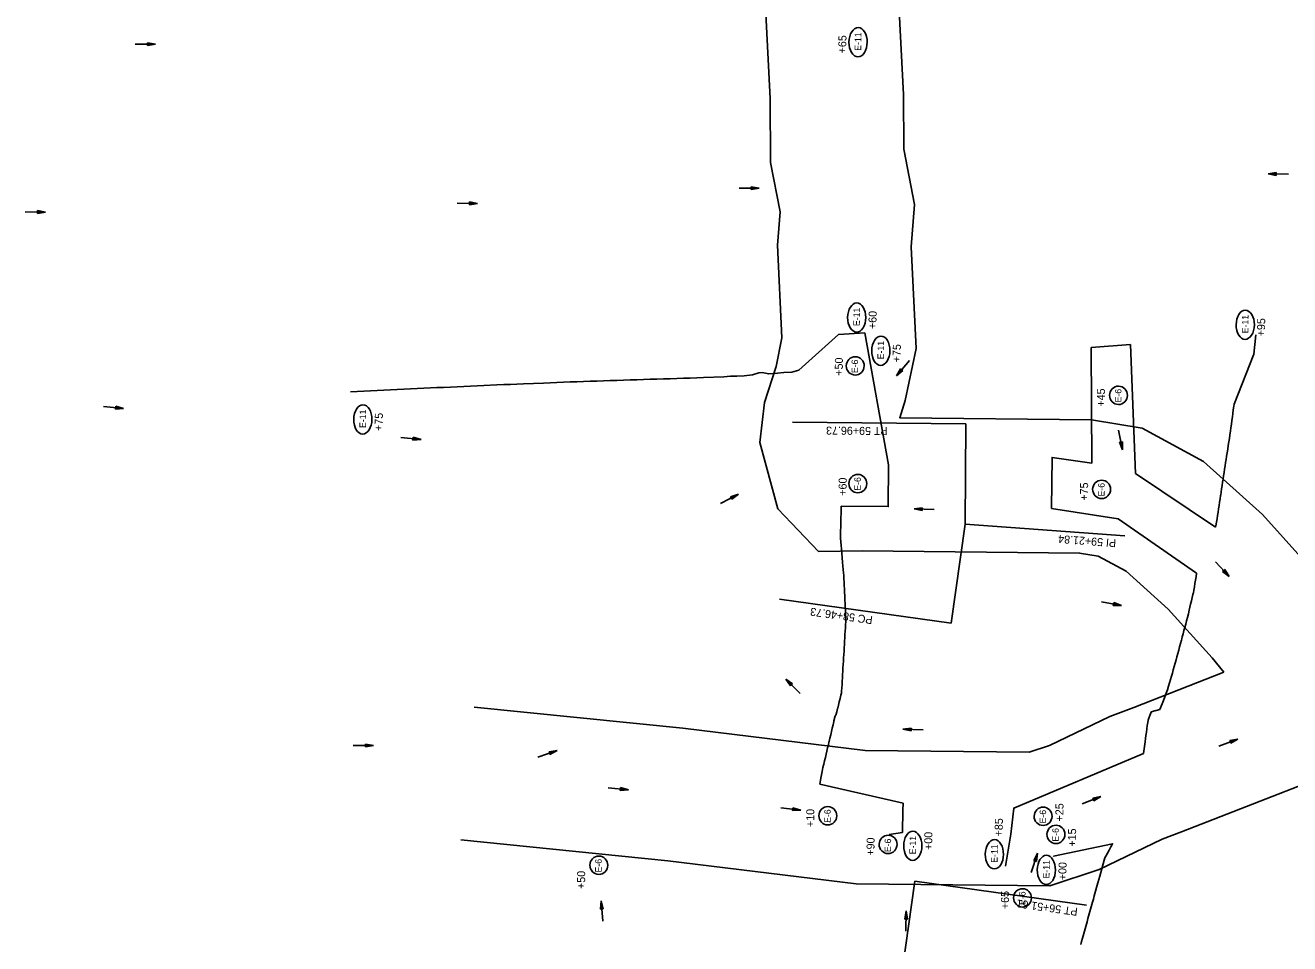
# Model space of a CAD drawing. Extents: x 1312891 to 1314734, y 2088044 to 2090982.
# Drawn here: x 1313292 to 1314240, y 2088726 to 2089414 of the extents above; entities that cross this region are included whole.
import ezdxf

# ---------------------------------------------------------------- set-up
doc = ezdxf.new("R2010")
doc.units = 0
for name, color, linetype in [('43', 7, 'Continuous'), ('44', 7, 'Continuous'), ('Level 1', 7, 'Continuous'), ('Level 44', 7, 'Continuous'), ('R_Buffer', 7, 'Continuous'), ('R_Horz Alg Annot_Detour', 7, 'Continuous')]:
    doc.layers.add(name, color=color, linetype=linetype)

msp = doc.modelspace()

# ---------------------------------------------------------------- linework, layer by layer
at = {"layer": '43'}
for p, q in [((1313383.35, 2089398.89), (1313383.37, 2089401.03)), ((1313389.43, 2089399.91), (1313383.35, 2089398.89)), ((1313383.37, 2089401.03), (1313389.43, 2089399.91)), ((1314223.52, 2089302.72), (1314229.6, 2089303.74)), ((1314229.59, 2089301.59), (1314223.52, 2089302.72)), ((1314229.6, 2089303.74), (1314229.59, 2089301.59)), ((1313835.91, 2089290.97), (1313835.93, 2089293.12)), ((1313842, 2089291.99), (1313835.91, 2089290.97)), ((1313835.93, 2089293.12), (1313842, 2089291.99)), ((1313624.72, 2089279.59), (1313624.74, 2089281.73)), ((1313630.8, 2089280.61), (1313624.72, 2089279.59)), ((1313624.74, 2089281.73), (1313630.8, 2089280.61)), ((1313300.87, 2089273.06), (1313300.89, 2089275.21)), ((1313306.96, 2089274.08), (1313300.87, 2089273.06)), ((1313300.89, 2089275.21), (1313306.96, 2089274.08)), ((1313944.75, 2089151.39), (1313947.91, 2089156.69)), ((1313949.53, 2089155.29), (1313944.75, 2089151.39)), ((1313947.91, 2089156.69), (1313949.53, 2089155.29)), ((1313359.29, 2089126.35), (1313359.53, 2089128.48)), ((1313365.45, 2089126.73), (1313359.29, 2089126.35)), ((1313359.53, 2089128.48), (1313365.45, 2089126.73)), ((1313582.31, 2089103.12), (1313582.55, 2089105.25)), ((1313588.47, 2089103.5), (1313582.31, 2089103.12)), ((1313582.55, 2089105.25), (1313588.47, 2089103.5)), ((1314112.13, 2089101.49), (1314114.24, 2089101.92)), ((1314114.4, 2089095.75), (1314112.13, 2089101.49)), ((1314114.24, 2089101.92), (1314114.4, 2089095.75)), ((1313820.44, 2089060.76), (1313826.32, 2089062.63)), ((1313821.43, 2089058.86), (1313820.44, 2089060.76)), ((1313826.32, 2089062.63), (1313821.43, 2089058.86)), ((1313958.03, 2089051.56), (1313964.14, 2089052.45)), ((1313964.07, 2089050.31), (1313958.03, 2089051.56)), ((1313964.14, 2089052.45), (1313964.07, 2089050.31)), ((1314189.34, 2089004.61), (1314190.9, 2089006.08)), ((1314194.27, 2089000.91), (1314189.34, 2089004.61)), ((1314190.9, 2089006.08), (1314194.27, 2089000.91)), ((1314107.3, 2088979.24), (1314107.69, 2088981.35)), ((1314113.46, 2088979.17), (1314107.3, 2088979.24)), ((1314107.69, 2088981.35), (1314113.46, 2088979.17)), ((1313861.82, 2088924), (1313866.88, 2088920.46)), ((1313865.36, 2088918.94), (1313861.82, 2088924)), ((1313866.88, 2088920.46), (1313865.36, 2088918.94)), ((1313949.72, 2088886.45), (1313955.83, 2088887.35)), ((1313955.76, 2088885.2), (1313949.72, 2088886.45)), ((1313955.83, 2088887.35), (1313955.76, 2088885.2)), ((1314194.65, 2088877.97), (1314200.72, 2088879.11)), ((1314200.72, 2088879.11), (1314195.41, 2088875.97)), ((1313546.72, 2088873.13), (1313546.74, 2088875.28)), ((1313552.8, 2088874.15), (1313546.72, 2088873.13)), ((1313546.74, 2088875.28), (1313552.8, 2088874.15)), ((1313684.38, 2088869.48), (1313690.47, 2088870.46)), ((1313685.08, 2088867.46), (1313684.38, 2088869.48)), ((1313690.47, 2088870.46), (1313685.08, 2088867.46)), ((1314195.41, 2088875.97), (1314194.65, 2088877.97)), ((1313737.7, 2088840.52), (1313737.95, 2088842.65)), ((1313743.86, 2088840.9), (1313737.7, 2088840.52)), ((1313737.95, 2088842.65), (1313743.86, 2088840.9)), ((1314092.09, 2088834.81), (1314098.16, 2088835.95)), ((1314092.85, 2088832.81), (1314092.09, 2088834.81)), ((1314098.16, 2088835.95), (1314092.85, 2088832.81)), ((1313867, 2088825.5), (1313867.24, 2088827.64)), ((1313873.16, 2088825.88), (1313867, 2088825.5)), ((1313867.24, 2088827.64), (1313873.16, 2088825.88)), ((1314047.71, 2088788.09), (1314050.68, 2088793.5)), ((1314050.68, 2088793.5), (1314049.74, 2088787.4)), ((1314049.74, 2088787.4), (1314047.71, 2088788.09)), ((1313722.88, 2088751.59), (1313723.47, 2088757.73)), ((1313723.47, 2088757.73), (1313725.02, 2088751.76)), ((1313725.02, 2088751.76), (1313722.88, 2088751.59)), ((1313951.01, 2088744.17), (1313952.17, 2088750.23)), ((1313952.17, 2088750.23), (1313953.15, 2088744.14)), ((1313953.15, 2088744.14), (1313951.01, 2088744.17))]:
    msp.add_line(p, q, dxfattribs=at)
for points in [[(1313374.25, 2089400.04), (1313389.43, 2089399.91)], [(1314238.71, 2089302.58), (1314223.52, 2089302.72)], [(1313826.81, 2089292.12), (1313842, 2089291.99)], [(1313615.62, 2089280.74), (1313630.8, 2089280.61)], [(1313291.77, 2089274.22), (1313306.96, 2089274.08)], [(1313954.67, 2089162.88), (1313944.75, 2089151.39)], [(1313350.36, 2089128.44), (1313365.45, 2089126.73)], [(1314111.36, 2089110.63), (1314114.4, 2089095.75)], [(1313573.38, 2089105.21), (1313588.47, 2089103.5)], [(1313812.86, 2089055.59), (1313826.32, 2089062.63)], [(1313973.21, 2089051.11), (1313958.03, 2089051.56)], [(1314183.9, 2089012), (1314194.27, 2089000.91)], [(1314098.54, 2088981.99), (1314113.46, 2088979.17)], [(1313872.56, 2088913.25), (1313861.82, 2088924)], [(1313964.9, 2088886.01), (1313949.72, 2088886.45)], [(1314186.5, 2088873.76), (1314200.72, 2088879.11)], [(1313537.62, 2088874.28), (1313552.8, 2088874.15)], [(1313676.12, 2088865.49), (1313690.47, 2088870.46)], [(1313728.77, 2088842.61), (1313743.86, 2088840.9)], [(1314083.94, 2088830.6), (1314098.16, 2088835.95)], [(1313858.07, 2088827.6), (1313873.16, 2088825.88)], [(1314045.8, 2088779.11), (1314050.68, 2088793.5)], [(1313724.68, 2088742.59), (1313723.47, 2088757.73)], [(1313951.95, 2088735.04), (1313952.17, 2088750.23)]]:
    msp.add_lwpolyline(points, dxfattribs=at)
at = {"layer": 'Level 1'}
for centre, major_axis, ratio in [((1313916.05, 2089401.39), (0.1, 10.96), 0.622952), ((1313915.02, 2089195.05), (0.1, 10.96), 0.622952), ((1314206.3, 2089189.59), (0.1, 10.96), 0.622952), ((1313933.12, 2089170.15), (0.1, 10.96), 0.622952), ((1313913.93, 2089158.78), (-0.05, -6.88), 0.97521), ((1314111.27, 2089136.72), (-0.05, -6.88), 0.97521), ((1313544.81, 2089118.67), (0.1, 10.96), 0.622952), ((1313915.87, 2089070.56), (-0.05, -6.88), 0.97521), ((1314098.63, 2089066.22), (-0.05, -6.88), 0.97521), ((1313893.37, 2088821.58), (-0.05, -6.88), 0.97521), ((1314054.76, 2088821.18), (-0.05, -6.88), 0.97521), ((1314064.39, 2088807.64), (-0.05, -6.88), 0.97521), ((1313938.58, 2088800.14), (-0.05, -6.88), 0.97521), ((1313957.08, 2088799.07), (0.1, 10.96), 0.622952), ((1314018.24, 2088792.71), (0.1, 10.96), 0.622952), ((1313721.73, 2088784.51), (-0.05, -6.88), 0.97521), ((1314057.2, 2088780.97), (0.1, 10.96), 0.622952), ((1314039.34, 2088760.06), (-0.05, -6.88), 0.97521)]:
    msp.add_ellipse(centre, major_axis=major_axis, ratio=ratio, dxfattribs=at)
at = {"layer": 'Level 44'}
for points in [[(1313921.2, 2089183.57), (1313901.47, 2089182.32), (1313871.6, 2089155.47)], [(1313921.2, 2089183.57), (1313938.94, 2089084.52), (1313938.67, 2089053.36), (1313903.27, 2089053.67)], [(1314184.04, 2089037.96), (1314184.24, 2089038.99), (1314184.73, 2089041.63), (1314185.14, 2089044.24), (1314185.53, 2089046.72), (1314185.92, 2089049.2), (1314186.3, 2089051.68), (1314186.68, 2089054.16), (1314187.07, 2089056.64), (1314187.45, 2089059.12), (1314187.82, 2089061.6), (1314187.91, 2089062.19), (1314188.2, 2089064.08), (1314188.57, 2089066.56), (1314188.95, 2089069.04), (1314189.32, 2089071.52), (1314189.69, 2089074), (1314190.06, 2089076.49), (1314190.42, 2089078.97), (1314190.78, 2089081.43), (1314191.15, 2089083.88), (1314191.51, 2089086.29), (1314191.9, 2089088.66), (1314192.32, 2089091.09), (1314192.76, 2089093.65), (1314193.18, 2089096.38), (1314193.58, 2089099.06), (1314193.99, 2089101.74), (1314194.38, 2089104.41), (1314194.77, 2089107.09), (1314195.16, 2089109.77), (1314195.54, 2089112.45), (1314195.91, 2089115.14), (1314196.28, 2089117.81), (1314196.65, 2089120.49), (1314197.01, 2089123.18), (1314197.37, 2089125.86), (1314197.72, 2089128.55), (1314197.91, 2089130), (1314212.7, 2089167.68), (1314214.29, 2089182.11), (1314214.29, 2089182.11)], [(1314061.11, 2089051.99), (1314061.44, 2089090.23), (1314091.2, 2089085.95), (1314091.2, 2089085.95), (1314091.2, 2089085.95), (1314090.86, 2089172.5), (1314120.27, 2089174.81), (1314124.07, 2089078.23)], [(1313871.6, 2089155.47), (1313866.33, 2089154.01), (1313860.44, 2089153.77), (1313855.7, 2089153.33), (1313849.16, 2089152.73), (1313844.11, 2089153.86), (1313841.75, 2089153.63), (1313837.03, 2089152.15), (1313830.67, 2089151.26), (1313825.13, 2089151.13), (1313820.38, 2089150.98), (1313815.42, 2089150.62), (1313800.25, 2089150.04), (1313795.24, 2089149.86), (1313790.24, 2089149.68), (1313785.25, 2089149.5), (1313780.23, 2089149.32), (1313775.13, 2089149.16), (1313770.15, 2089149.08), (1313765.24, 2089148.91), (1313760.25, 2089148.73), (1313755.23, 2089148.56), (1313750.19, 2089148.4), (1313745.19, 2089148.27), (1313740.24, 2089148.11), (1313735.26, 2089147.93), (1313730.21, 2089147.75), (1313725.23, 2089147.63), (1313720.26, 2089147.43), (1313715.24, 2089147.27), (1313710.27, 2089147.1), (1313705.28, 2089146.92), (1313700.32, 2089146.73), (1313695.33, 2089146.52), (1313690.31, 2089146.33), (1313685.3, 2089146.14), (1313680.31, 2089145.95), (1313665.32, 2089145.37), (1313660.35, 2089145.18), (1313655.4, 2089144.96), (1313650.39, 2089144.73), (1313645.38, 2089144.53), (1313635.44, 2089144.11), (1313630.47, 2089143.85), (1313625.46, 2089143.61), (1313620.51, 2089143.36), (1313610.41, 2089142.82), (1313605.29, 2089142.67), (1313600.4, 2089142.52), (1313595.52, 2089142.29), (1313590.55, 2089142.02), (1313585.51, 2089141.75), (1313580.46, 2089141.53), (1313575.51, 2089141.31), (1313565.57, 2089140.8), (1313560.49, 2089140.53), (1313555.47, 2089140.35), (1313550.52, 2089140.11), (1313535.59, 2089139.46)], [(1314124.07, 2089078.23), (1314184.04, 2089037.96)], [(1313903.27, 2089053.67), (1313903.35, 2089050.14), (1313903.32, 2089047.91), (1313903.23, 2089045.44), (1313903.18, 2089042.84), (1313903.14, 2089040.36), (1313902.95, 2089032.8), (1313902.92, 2089029.76), (1313903.36, 2089024.24), (1313903.56, 2089021.73), (1313904.32, 2089011.58), (1313904.54, 2089008.7), (1313905.26, 2089003.75)], [(1314129.98, 2088868.26), (1314131.19, 2088876.9), (1314131.54, 2088879.39), (1314131.88, 2088881.87), (1314132.23, 2088884.36), (1314132.57, 2088886.84), (1314132.9, 2088889.27), (1314133.22, 2088891.42), (1314133.6, 2088893.28), (1314134.03, 2088894.85), (1314134.79, 2088896.75), (1314135.75, 2088899.16), (1314135.83, 2088899.37), (1314142.23, 2088901.14), (1314145.07, 2088908.1), (1314146.1, 2088910.64), (1314147.13, 2088913.39), (1314148, 2088916.07), (1314148.81, 2088918.64), (1314149.56, 2088921.21), (1314150.27, 2088923.69), (1314150.96, 2088926.13), (1314151.65, 2088928.58), (1314152.34, 2088931.02), (1314153.03, 2088933.47), (1314153.72, 2088935.92), (1314154.4, 2088938.36), (1314155.08, 2088940.81), (1314155.76, 2088943.26), (1314156.44, 2088945.71), (1314157.12, 2088948.16), (1314157.79, 2088950.63), (1314158.46, 2088953.1), (1314158.76, 2088954.22), (1314159.13, 2088955.67), (1314159.73, 2088958.07), (1314160.35, 2088960.38), (1314161.02, 2088962.75), (1314161.71, 2088965.19), (1314162.39, 2088967.64), (1314163.11, 2088970.19), (1314163.84, 2088973.05), (1314164.36, 2088975.78), (1314164.8, 2088978.02), (1314165.34, 2088980.28), (1314165.92, 2088982.68), (1314166.51, 2088985.1), (1314167.12, 2088987.55), (1314167.26, 2088988.13), (1314167.42, 2088988.78), (1314167.75, 2088990.64), (1314168.2, 2088993.13), (1314168.63, 2088995.63), (1314169.06, 2088998.15), (1314169.49, 2089000.75), (1314169.86, 2089003.35), (1314111.16, 2089044.05), (1314061.11, 2089051.99)], [(1313905.26, 2089003.75), (1313905.35, 2089001.73), (1313905.46, 2088999.2), (1313905.57, 2088996.64), (1313905.7, 2088994.09), (1313905.82, 2088991.57), (1313905.93, 2088989.07), (1313906.05, 2088986.53), (1313906.16, 2088984), (1313906.23, 2088982.55), (1313906.28, 2088981.44), (1313906.41, 2088978.94), (1313906.61, 2088973.94), (1313906.72, 2088971.4), (1313906.81, 2088969.06), (1313906.82, 2088967.05), (1313906.69, 2088964.88), (1313906.54, 2088962.37), (1313906.39, 2088959.86), (1313906.24, 2088957.36), (1313906.1, 2088954.86), (1313905.95, 2088952.35), (1313905.81, 2088949.84), (1313905.67, 2088947.34), (1313905.53, 2088944.85), (1313905.38, 2088942.4), (1313905.22, 2088939.92), (1313905.06, 2088937.38), (1313904.91, 2088934.88), (1313904.76, 2088932.37), (1313904.62, 2088929.87), (1313904.47, 2088927.36), (1313904.33, 2088924.86), (1313904.18, 2088922.35), (1313904.04, 2088919.87), (1313903.89, 2088917.41), (1313903.73, 2088914.88), (1313903.65, 2088913.36), (1313903.26, 2088911.89), (1313902.62, 2088909.42), (1313901.98, 2088906.96), (1313901.34, 2088904.49), (1313900.78, 2088902.26), (1313900.71, 2088902.01), (1313900.09, 2088899.55), (1313899.46, 2088897.02), (1313898.88, 2088896.39), (1313897.98, 2088892.66), (1313897.86, 2088892.16), (1313897.27, 2088889.7), (1313896.68, 2088887.23), (1313896.1, 2088884.76), (1313895.52, 2088882.29), (1313894.95, 2088879.82), (1313894.38, 2088877.35), (1313894.26, 2088876.85), (1313893.81, 2088874.87), (1313893.26, 2088872.4), (1313892.73, 2088870.06), (1313892.16, 2088867.74), (1313891.54, 2088865.3), (1313890.92, 2088862.84), (1313890.31, 2088860.38), (1313889.64, 2088857.64), (1313889.12, 2088854.87), (1313888.66, 2088852.37), (1313888.22, 2088849.89), (1313887.41, 2088845.35), (1313949.75, 2088830.93)], [(1314026.65, 2088783.78), (1314030.52, 2088807.76), (1314032.73, 2088827.37), (1314129.98, 2088868.26)], [(1313949.75, 2088830.93), (1313949.7, 2088825.84), (1313949.32, 2088809.12), (1313939.25, 2088807.64)], [(1314082.98, 2088725.07), (1314083.64, 2088727.39), (1314084.35, 2088729.86), (1314087.74, 2088742.11), (1314088.42, 2088744.55), (1314091.8, 2088756.75), (1314092.48, 2088759.19), (1314093.16, 2088761.64), (1314095.85, 2088771.4), (1314096.51, 2088773.8), (1314097.21, 2088776.24), (1314100.57, 2088788.42), (1314101.01, 2088789.94), (1314101.7, 2088791.33), (1314104.2, 2088795.88), (1314105.49, 2088798.24), (1314106.8, 2088800.6), (1314062.46, 2088791.33), (1314062.46, 2088791.33)]]:
    msp.add_lwpolyline(points, dxfattribs=at)
at = {"layer": 'R_Buffer'}
for points in [[(1314398.07, 2088926.4), (1314279.08, 2088981.02), (1314219.25, 2089047.46), (1314174.9, 2089087.16), (1314129.03, 2089112.05), (1314090.93, 2089118.43), (1313947.29, 2089119.91), (1313951.49, 2089132.93), (1313959.52, 2089171.91), (1313955.89, 2089247.91), (1313958.34, 2089279.86), (1313950.38, 2089321.29), (1313950.04, 2089362.11), (1313946.13, 2089439.68), (1313939.37, 2089474.77), (1313935.33, 2089518.66), (1313906.32, 2089564.88), (1313890.91, 2089585.64), (1313842.78, 2089656.54), (1313803.18, 2089711.63), (1313763.93, 2089776.35), (1313748.13, 2089794.9), (1313663.53, 2089824.18)], [(1314190.14, 2088929.12), (1314181.4, 2088940.05), (1314148.54, 2088976.54), (1314116.93, 2089004.84), (1314096.02, 2089016.18), (1314082.1, 2089018.52), (1313919.02, 2089020.19), (1313886.42, 2089019.59), (1313855.95, 2089051.66), (1313842.49, 2089101.4), (1313845.88, 2089131.29), (1313854.65, 2089158.45), (1313859.03, 2089179.73), (1313855.71, 2089249.36), (1313857.61, 2089274.15), (1313850.46, 2089311.35), (1313850.06, 2089359.17), (1313846.61, 2089427.64)], [(1314190.14, 2088929.12), (1314122.8, 2088902.8), (1314104.78, 2088896.02), (1314059.46, 2088874.32), (1314044.29, 2088869.32), (1313921.3, 2088870.45), (1313784.65, 2088887.22), (1313628.26, 2088902.96)], [(1314295.86, 2088863.28), (1314241.12, 2088841.68), (1314158.61, 2088809.43), (1314144.05, 2088803.95), (1314096.86, 2088781.35), (1314059.89, 2088769.17), (1313914.73, 2088770.51), (1313773.56, 2088787.83), (1313618.24, 2088803.47)]]:
    msp.add_lwpolyline(points, dxfattribs=at)
at = {"layer": 'R_Horz Alg Annot_Detour'}
for points in [[(1313996.9, 2089115.37), (1313866.91, 2089116.51)], [(1313985.8, 2088965.89), (1313996.25, 2089040.27), (1313996.9, 2089115.37)], [(1313996.25, 2089040.27), (1314115.92, 2089031.38)], [(1313985.8, 2088965.89), (1313857.06, 2088983.99)], [(1313956.03, 2088473.54), (1313937.64, 2088623.28), (1313958.64, 2088772.67)], [(1313958.64, 2088772.67), (1314087.38, 2088754.58)]]:
    msp.add_lwpolyline(points, dxfattribs=at)

# ---------------------------------------------------------------- texts
at = {"layer": '44'}
for s, rotation, p in [('+65', 88.324, (1313907.03, 2089392.97)), ('+60', 88.324, (1313929.68, 2089186.31)), ('+95', 88.324, (1314220.96, 2089180.85)), ('+75', 88.324, (1313947.79, 2089161.41)), ('+50', 89.5, (1313904.58, 2089151.4)), ('+45', 89.5, (1314101.04, 2089128.24)), ('+75', 88.324, (1313559.48, 2089109.93)), ('+60', 89.5, (1313907.43, 2089061.43)), ('+75', 89.5, (1314088.4, 2089057.74)), ('+10', 89.5, (1313883.14, 2088813.1)), ('+25', 89.5, (1314069.95, 2088817.3)), ('+85', 88.324, (1314024.29, 2088806.03)), ('+15', 89.5, (1314079.41, 2088798.42)), ('+90', 89.5, (1313928.36, 2088791.66)), ('+00', 89.5, (1313971.64, 2088795.93)), ('+00', 88.324, (1314072.05, 2088773.17)), ('+50', 89.5, (1313711.41, 2088766.67)), ('+65', 89.5, (1314029.11, 2088751.59))]:
    msp.add_text(s, height=6, rotation=rotation, dxfattribs=at).set_placement(p)
at = {"layer": 'Level 1'}
for s, rotation, p in [('E-11 ', 89.5, (1313918.39, 2089394.97)), ('E-11 ', 89.5, (1313917.36, 2089188.63)), ('E-11 ', 89.5, (1314208.64, 2089183.18)), ('E-11 ', 89.5, (1313935.46, 2089163.73)), ('E-6 ', 89.55802, (1313916.01, 2089153.34)), ('E-6 ', 89.55802, (1314113.45, 2089131.38)), ('E-11 ', 89.5, (1313547.15, 2089112.25)), ('E-6 ', 89.55802, (1313918.05, 2089065.22)), ('E-6 ', 89.55802, (1314100.81, 2089060.88)), ('E-6 ', 89.55802, (1313895.55, 2088816.24)), ('E-6 ', 89.55802, (1314056.94, 2088815.84)), ('E-6 ', 89.55802, (1314066.48, 2088802.2)), ('E-6 ', 89.55802, (1313940.76, 2088794.28)), ('E-11 ', 89.5, (1313959.42, 2088792.66)), ('E-11 ', 89.5, (1314020.58, 2088786.29)), ('E-6 ', 89.55802, (1313723.81, 2088779.07)), ('E-11 ', 89.5, (1314059.54, 2088774.56)), ('E-6 ', 89.55802, (1314041.52, 2088754.72))]:
    msp.add_text(s, height=4.876, rotation=rotation, dxfattribs=at).set_placement(p)
at = {"layer": 'R_Horz Alg Annot_Detour'}
for s, rotation, p in [('PT 59+96.73', 179.5, (1313938.25, 2089112.89)), ('PI 59+21.84', 175.75, (1314109.71, 2089028.83)), ('PC 58+46.73', 172, (1313927.32, 2088971.08)), ('PT 56+51.61', 172, (1314081.02, 2088752.44))]:
    msp.add_text(s, height=6, rotation=rotation, dxfattribs=at).set_placement(p)

doc.saveas('drawing.dxf')
